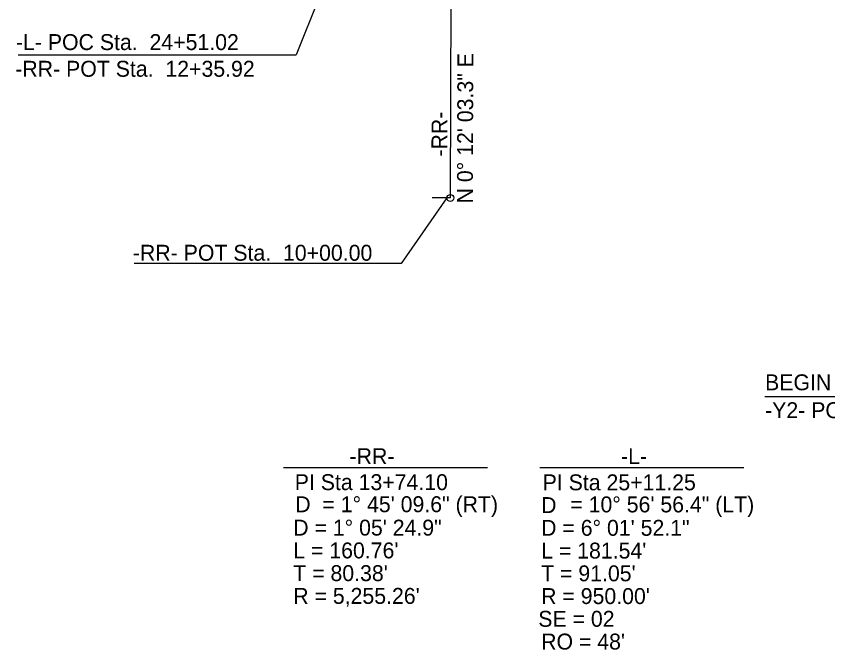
# Model space of a CAD drawing. Extents: x 1755545 to 1761252, y 736169 to 737766.
# Drawn here: x 1756943.4 to 1757300.5, y 736544.4 to 736822.9 of the extents above; entities that cross this region are included whole.
import ezdxf

# ---------------------------------------------------------------- set-up
doc = ezdxf.new("R2010")
doc.units = 0
for name, color, linetype in [('Exist Horizontal Alignment Curve and Spiral Data', 7, 'Continuous'), ('Exist Horizontal Alignment Direction Label', 7, 'Continuous'), ('Exist Horizontal Alignment Station Label', 7, 'Continuous'), ('Exist Horizontal Alignment Tick Large', 7, 'Continuous'), ('Prop Horizontal Alignment Curve and Spiral Data', 7, 'Continuous'), ('Prop Horizontal Alignment Station Label', 7, 'Continuous'), ('Raster_Level_0', 7, 'Continuous')]:
    doc.layers.add(name, color=color, linetype=linetype)

msp = doc.modelspace()

# ---------------------------------------------------------------- linework, layer by layer
at = {"layer": 'Exist Horizontal Alignment Curve and Spiral Data'}
msp.add_line((1757060.98, 736624.49), (1757150.74, 736624.49), dxfattribs=at)
at = {"layer": 'Exist Horizontal Alignment Station Label'}
for p, q in [((1757135.27, 736978.92), (1757066.64, 736805.99)), ((1756944.29, 736805.99), (1757066.64, 736805.99)), ((1757132.94, 736743.01), (1757112.84, 736714.19)), ((1757112.84, 736714.19), (1756995.26, 736714.19))]:
    msp.add_line(p, q, dxfattribs=at)
msp.add_circle((1757134.44, 736743), 1.5, dxfattribs=at)
at = {"layer": 'Exist Horizontal Alignment Tick Large'}
msp.add_line((1757134.44, 736743), (1757126.44, 736743.03), dxfattribs=at)
at = {"layer": 'Prop Horizontal Alignment Curve and Spiral Data'}
msp.add_line((1757173.78, 736624.49), (1757263.54, 736624.49), dxfattribs=at)
at = {"layer": 'Prop Horizontal Alignment Station Label'}
msp.add_line((1757272.78, 736655.79), (1757386.1, 736655.79), dxfattribs=at)
at = {"layer": 'Raster_Level_0'}
msp.add_line((1757134.44, 736743), (1757135.47, 737036.72), dxfattribs=at)

# ---------------------------------------------------------------- texts
at = {"layer": 'Exist Horizontal Alignment Curve and Spiral Data'}
for s, p in [('-RR-', (1757090.09, 736625.99)), ('PI Sta 13+74.10', (1757065.98, 736614.57)), ('D', (1757066.2, 736604.83)), ('= 1%%d 45\' 09.6" (RT)', (1757078.16, 736604.87)), ('D = 1%%d 05\' 24.9"', (1757065.31, 736594.57)), ("L = 160.76'", (1757065.31, 736584.57)), ("T = 80.38'", (1757065.31, 736574.57)), ("R = 5,255.26'", (1757065.31, 736564.57))]:
    msp.add_text(s, height=7, dxfattribs=at).set_placement(p)
at = {"layer": 'Exist Horizontal Alignment Direction Label'}
for s, p in [('N 0%%d 12\' 03.3" E', (1757144.34, 736740.59)), ('-RR-', (1757133.11, 736761.17))]:
    msp.add_text(s, height=7, rotation=89.7991, dxfattribs=at).set_placement(p)
at = {"layer": 'Exist Horizontal Alignment Station Label'}
for s, p in [('-L- POC Sta.  24+51.02', (1756943.29, 736808.02)), ('-RR- POT Sta.  10+00.00', (1756994.75, 736715.41))]:
    msp.add_text(s, height=7, rotation=360, dxfattribs=at).set_placement(p)
msp.add_text('-RR- POT Sta.  12+35.92', height=7, dxfattribs=at).set_placement((1756943.01, 736796.29))
at = {"layer": 'Prop Horizontal Alignment Curve and Spiral Data'}
for s, p in [('-L-', (1757209.53, 736625.99)), ('PI Sta 25+11.25', (1757175.05, 736614.49)), ('D', (1757174.38, 736604.49)), ('= 10%%d 56\' 56.4" (LT)', (1757187.23, 736604.79)), ('D = 6%%d 01\' 52.1"', (1757174.38, 736594.49)), ("L = 181.54'", (1757174.38, 736584.49)), ("T = 91.05'", (1757174.38, 736574.49)), ("R = 950.00'", (1757174.38, 736564.49)), ('SE = 02', (1757173.12, 736554.49)), ("RO = 48'", (1757174.38, 736544.49))]:
    msp.add_text(s, height=7, dxfattribs=at).set_placement(p)
at = {"layer": 'Prop Horizontal Alignment Station Label'}
for s, p in [('BEGIN CONSTRUCTION', (1757272.93, 736658.46)), ('-Y2- POT Sta.  11+25.00', (1757272.93, 736646.21))]:
    msp.add_text(s, height=7, rotation=360, dxfattribs=at).set_placement(p)

doc.saveas('drawing.dxf')
